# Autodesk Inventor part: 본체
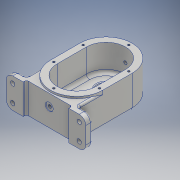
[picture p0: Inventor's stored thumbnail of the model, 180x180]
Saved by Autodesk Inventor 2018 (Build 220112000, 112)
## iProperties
Created: 2021-05
Part Number: 본체
Material: 알루미늄 6061
Document SubType Name: Modeling
Designer: admin
Mass: 756.755 g
Surface Area: 581.834 cm^2
Volume: 280.28 cm^3
Density: 2.7 g/cm^3
Appearance: 알루미늄 - 평지
Author: admin
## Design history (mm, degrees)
sketch "스케치1"
  geometry: L1 (0, 0)-(0, 45); L2 (-40, 0)-(-40, 45); L3 (40, 45)-(40, 0); A1 r 40 centre (0, 0) between (-40, 0) and (40, 0); A2 r 40 centre (0, 45) between (40, 45) and (-40, 45); 1 further point
  constraints: 8 end point, 4 point on circle, 4 tangent, 2 centre point, 1 midpoint, 1 parallel, 1 vertical
  dimensions: "d0" = 80 distance between parallel lines of L2 L3; "d1" = 45 distance of L1.start L1.end
extrude "돌출1" new body sketch "스케치1" stored distance "d2" = 49; taper "d3" = 0 deg
node "작업 평면1"
sketch "스케치2"
  geometry: L1 (-61, -24.5)-(61, -24.5); L2 (61, -24.5)-(61, 21.5); L3 (61, 21.5)-(-61, 21.5); L4 (-61, 21.5)-(-61, -24.5); L5 (40, 24.5)-(-40, 24.5) reference; L6 (-40, -24.5)-(40, -24.5) reference; L7 (0, -34.3)-(0, 34.3) reference; 2 further points
  constraints: 8 end point, 2 midpoint, 2 parallel, 1 horizontal, 1 perpendicular, 1 other
  dimensions: "d5" = 122 distance of L2.end L3.end; "d6" = 46 distance of L1.end L2.end
extrude "돌출2" join sketch "스케치2" distance "d7" = 10; taper "d8" = 0 deg
sketch "스케치3"
  geometry: L1 (0, 0)-(122, 0) reference; L2 (26, 0)-(96, 0); L3 (96, 0)-(96, 5); L4 (96, 5)-(26, 5); L5 (26, 5)-(26, 0); L6 (61, -26.4)-(61, 158.4) reference; 1 further point
  constraints: 8 end point, 2 parallel, 1 horizontal, 1 perpendicular, 1 point on line, 1 other
  dimensions: "d9" = 70 distance of L3.end L4.end; "d10" = 5 distance of L2.end L3.end
extrude "돌출3" cut sketch "스케치3" distance "d11" = 100; taper "d12" = 0 deg
sketch "스케치4"
  geometry: L1 (35, 24.5)-(-35, 24.5) reference; L2 (35, -21.5)-(61, -21.5) reference; L3 (-40, 24.5)-(40, 24.5); L4 (40, 24.5)-(40, -21.5); L5 (40, -21.5)-(-40, -21.5); L6 (-40, -21.5)-(-40, 24.5); 1 further point
  constraints: 8 end point, 2 parallel, 2 point on line, 1 horizontal, 1 perpendicular
  dimensions: "d13" = 80 distance between parallel lines of L6 L4; "d14" = 40 distance from line of L4 point (0, 0)
extrude "돌출4" join sketch "스케치4" distance "d15" = 40; taper "d16" = 0 deg
sketch "스케치5"
  geometry: L1 (0, 0)-(0, 45); L2 (-30, 0)-(-30, 45); L3 (30, 45)-(30, 0); A1 r 30 centre (0, 0) between (-30, 0) and (30, 0); A2 r 30 centre (0, 45) between (30, 45) and (-30, 45); 1 further point
  constraints: 8 end point, 4 point on circle, 4 tangent, 2 centre point, 1 midpoint, 1 parallel, 1 vertical
  dimensions: "d17" = 60 distance between parallel lines of L3 L2; "d18" = 45 distance of L1.start L1.end
extrude "돌출5" cut sketch "스케치5" distance "d19" = 41; taper "d20" = 0 deg
sketch "스케치6"
  geometry: L1 (0, 0)-(0, 45); L2 (-26, 0)-(-26, 45); L3 (26, 45)-(26, 0); A1 r 26 centre (0, 0) between (-26, 0) and (26, 0); A2 r 26 centre (0, 45) between (26, 45) and (-26, 45); 1 further point
  constraints: 8 end point, 4 point on circle, 4 tangent, 2 centre point, 1 midpoint, 1 parallel, 1 vertical
  dimensions: "d21" = 45 distance of L1.start L1.end; "d22" = 26 radius of A2
extrude "돌출6" join sketch "스케치6" distance "d23" = 11; taper "d24" = 0 deg
sketch "스케치7"
  geometry: L1 (-26, 45)-(-26, 0) reference; L2 (26, 0)-(26, 45) reference; L3 (-26, 0)-(-26, 45) reference; L4 (-26, 15)-(26, 15); L5 (-26, 15)-(-26, 45); L6 (26, 15)-(26, 45); A1 r 26 centre (0, 45) between (26, 45) and (-26, 45) reference; A2 r 26 centre (0, 45) between (26, 45) and (-26, 45) reference; A3 r 26 centre (0, 45) between (26, 45) and (-26, 45); 2 further points
  constraints: 6 end point, 2 coincident, 2 collinear, 2 point on circle, 2 point on line, 1 centre point, 1 horizontal alignment, 1 perpendicular, 3 other
  dimensions: "d25" = 30 distance from line of A1.centre L4
extrude "돌출7" cut sketch "스케치7" distance "d26" = 3; taper "d27" = 0 deg
sketch "스케치8"
  geometry: L1 (-30, 0)-(-30, 45) reference; L2 (30, 45)-(30, 0) reference; C1 r 14 at (0, 45); C2 r 14 at (0, 0); A1 r 30 centre (0, 0) between (-30, 0) and (30, 0) reference; A2 r 30 centre (0, 45) between (30, 45) and (-30, 45) reference; A3 r 30 centre (0, 0) between (-30, 0) and (30, 0) reference; 1 further point
  constraints: 2 centre point, 2 coincident
  dimensions: "d28" = 28 diameter of C1; "d29" = 28 diameter of C2
extrude "돌출8" cut sketch "스케치8" distance "d30" = 8; taper "d31" = 0 deg
sketch "스케치9"
  geometry: C1 r 10 at (0, 0); 1 further point
  constraints: 1 centre point, 1 coincident
  dimensions: "d32" = 20 diameter of C1
extrude "돌출9" cut sketch "스케치9" distance "d33" = 4; taper "d34" = 0 deg
sketch "스케치10"
  geometry: L1 (-26, 15)-(-26, 45) reference; L2 (26, 15)-(-26, 15) reference; L3 (26, 45)-(26, 15) reference; C1 r 14 at (0, 45); A1 r 26 centre (0, 45) between (26, 45) and (-26, 45) reference; 1 further point
  constraints: 1 centre point, 1 coincident
  dimensions: "d35" = 28 diameter of C1
extrude "돌출10" cut sketch "스케치10" distance "d36" = 4; taper "d37" = 0 deg
sketch "스케치11"
  geometry: L1 (-26, -30)-(-26, 0) reference; L2 (26, -30)-(-26, -30) reference; L3 (26, 0)-(26, -30) reference; C1 r 14 at (0, 0) reference; C2 r 11 at (0, 0); A1 r 26 centre (0, 0) between (26, 0) and (-26, 0) reference; 1 further point
  constraints: 1 centre point, 1 coincident
  dimensions: "d38" = 22 diameter of C2
extrude "돌출11" cut sketch "스케치11" distance "d39" = 20; taper "d40" = 0 deg
fillet "모깎기1" dims "d41" = 10
sketch "스케치12"
  geometry: A1 r 10 centre (-51, 14.5) between (-51, 24.5) and (-61, 14.5) reference; A2 r 10 centre (-51, -11.5) between (-61, -11.5) and (-51, -21.5) reference; A3 r 10 centre (51, 14.5) between (61, 14.5) and (51, 24.5) reference; A4 r 10 centre (51, -11.5) between (51, -21.5) and (61, -11.5) reference; 5 further points
  constraints: 4 coincident
hole "구멍1" sketch "스케치12" at (-51, 14.5), (-51, -11.5), (51, -11.5), (51, 14.5) diameter "d42" = 6.6; stored, may be unused: countersink angle "d46" = 90 deg, drill point angle "d48" = 118 deg; dims "d43" = 6, "d44" = 11, "d45" = 2, "d47" = 8
sketch "스케치13"
  geometry: L1 (75, 3)-(-5, 3) reference; 2 further points
  constraints: 1 vertical alignment
  dimensions: "d49" = 21 distance from line of point (35, -18) L1
hole "구멍2" sketch "스케치13" at (35, -18) diameter "d50" = 4.917; stored, may be unused: countersink angle "d54" = 90 deg, drill point angle "d56" = 118 deg; dims "d51" = 17.1, "d52" = 12, "d53" = 1, "d55" = 17.1
sketch "스케치14"
  geometry: C1 r 11 at (0, 45) reference; C2 r 14 at (0, 45) reference; 2 further points
  constraints: 1 vertical alignment
  dimensions: "d57" = 20 distance of C1.centre point (0, 65)
hole "구멍3" sketch "스케치14" at (0, 65) diameter "d58" = 3.242; stored, may be unused: countersink angle "d62" = 90 deg, drill point angle "d64" = 118 deg; dims "d59" = 8, "d60" = 12, "d61" = 1, "d63" = 10
sketch "스케치15"
  geometry: L1 (0, 0)-(0, 45); L2 (35, 0)-(35, 45); L3 (-35, 45)-(-35, 0); C1 r 11 at (0, 45) reference; A1 r 35 centre (0, 0) between (-35, 0) and (35, 0); A2 r 35 centre (0, 45) between (35, 45) and (-35, 45); 7 further points
  constraints: 8 end point, 5 point on circle, 4 coincident, 4 tangent, 2 centre point, 1 midpoint, 1 parallel, 1 vertical, 1 vertical alignment
  dimensions: "d68" = 35 distance of point (0, 80) L1.end; "d76" = 70 diameter of A2
hole "구멍4" sketch "스케치15" at (0, 80), (35, 45), (35, 0), (0, -35), (-35, 0), (-35, 45) diameter "d69" = 3.242; stored, may be unused: countersink angle "d73" = 90 deg, drill point angle "d75" = 118 deg; dims "d70" = 8, "d71" = 12, "d72" = 1, "d74" = 10
node "작업 평면2"
sketch "스케치16"
  geometry: L1 (40, 24.5)-(-40, 24.5) reference; C1 r 6 at (0, 3.5); 1 further point
  constraints: 1 centre point, 1 vertical alignment
  dimensions: "d78" = 12 diameter of C1; "d79" = 21 distance from line of C1.centre L1
extrude "돌출12" join sketch "스케치16" stored distance "d80" = 20; taper "d81" = 0 deg
sketch "스케치17"
  geometry: C1 r 6 at (0, 0) reference; 2 further points
  constraints: 1 coincident
hole "구멍5" sketch "스케치17" at (0, 0) diameter "d82" = 4.917; stored, may be unused: countersink angle "d86" = 90 deg, drill point angle "d88" = 118 deg; dims "d83" = 17, "d84" = 12, "d85" = 1, "d87" = 17
fillet "모깎기2" dims "d89" = 0.3
fillet "모깎기3" dims "d90" = 5
fillet "모깎기4" dims "d91" = 3
chamfer "모따기1" distance "d92" = 1; stored, may be unused: second distance "d93" = 2, angle "d94" = 45 deg
sketch "스케치18"
  geometry: L1 (35, -47)-(51, -47) reference; L2 (-35, -42)-(35, -42) reference; 3 further points
  constraints: 1 midpoint, 1 vertical alignment, 1 other
  dimensions: "d95" = 12 distance from line of point (0, -35) L1
feature "엠보싱1" sketch "스케치18" dims "d96" = 0.5, "d97" = 0
fillet "모깎기5" dims "d98" = 3
node "솔리드1"
pattern_circular "원형 패턴1" dims angle "d66" = 360 deg
node "투영된 루프1"
node "투영된 루프2"
node "투영된 루프3"
node "투영된 루프4"
other parameters: "d4" = -47, "d77" = 88
